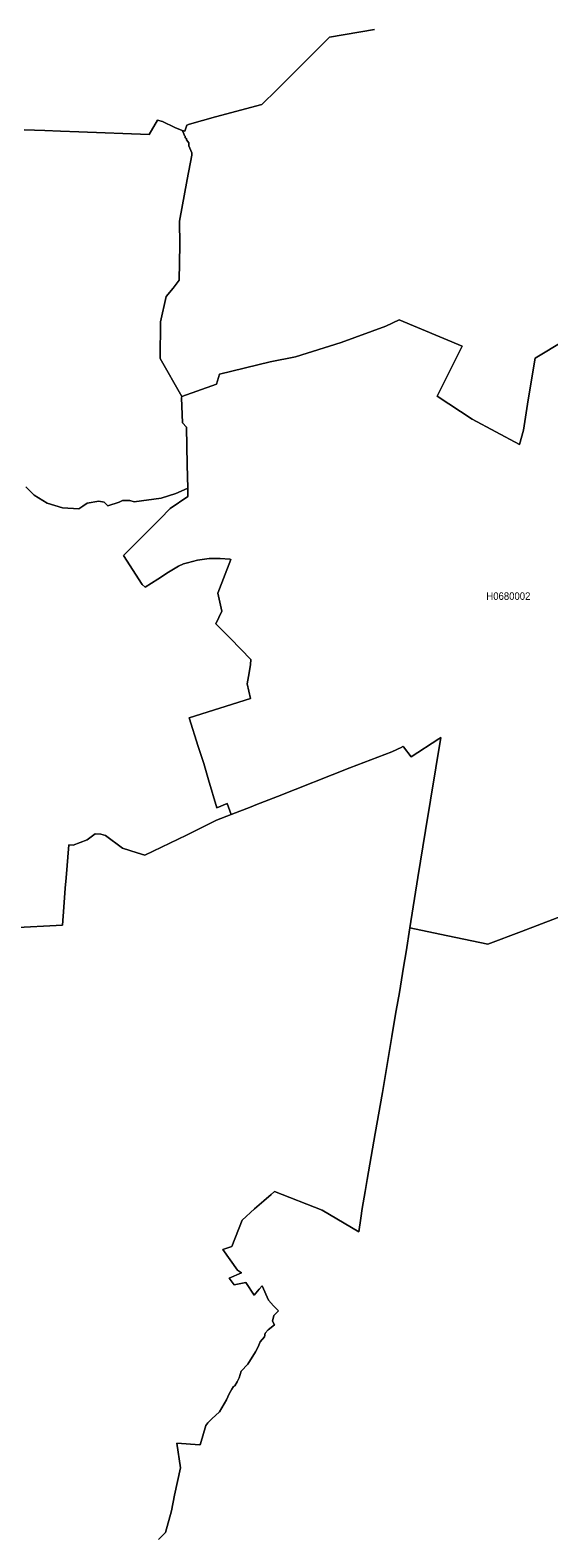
# Model space of a CAD drawing. Extents: x 369010 to 739155, y 6377141 to 6616555.
# Drawn here: x 495056 to 501969, y 6526211 to 6546276 of the extents above; entities that cross this region are included whole.
import ezdxf
from ezdxf.enums import TextEntityAlignment as Align

# ---------------------------------------------------------------- set-up
doc = ezdxf.new("R2010")
doc.units = 0
doc.header["$LTSCALE"] = 40
doc.layers.add('1', color=7, linetype='Continuous', lineweight=13)
doc.layers.add('2', color=7, linetype='Continuous')

msp = doc.modelspace()

# ---------------------------------------------------------------- linework, layer by layer
at = {"layer": '1'}
for points in [[(494977.62, 6544949.63), (495250.2, 6544939.2), (495459.07, 6544933.74), (495704.18, 6544923.31), (496644.41, 6544888.23), (496753.97, 6545079.05), (496821.83, 6545059.36), (496984.85, 6544979.42), (497082.5, 6544941.85), (497116.09, 6544933.41), (497145.88, 6545010.37), (497181.3, 6545026.09), (497527.04, 6545121.75), (498143.38, 6545286.1), (498343.47, 6545480.9), (498691.36, 6545828.12), (499045.54, 6546180.65), (499644.5, 6546285.25)], [(499644.5, 6546285.25), (499045.54, 6546180.65), (498691.36, 6545828.12), (498343.47, 6545480.9), (498143.38, 6545286.1), (497527.04, 6545121.75), (497181.3, 6545026.09), (497145.88, 6545010.37), (497116.09, 6544933.41), (497082.5, 6544941.85), (497103.35, 6544898.98), (497106.66, 6544876.48), (497124.2, 6544865.55), (497120.73, 6544843.71), (497141.25, 6544835.93), (497140.26, 6544818.38), (497171.21, 6544774.36), (497172.2, 6544735.63), (497209.44, 6544644.6), (497209.93, 6544614.15), (497147.7, 6544286.95), (497044.76, 6543735.49), (497051.05, 6543419.54), (497042.44, 6542947.36), (496963.66, 6542844.09), (496868.66, 6542731.05), (496793.03, 6542395.74), (496790.88, 6541908.33), (497076.37, 6541398.91), (497539.95, 6541563.91), (497579.5, 6541699.46), (498255.59, 6541862.65), (498592.39, 6541927.86), (499203.26, 6542118.85), (499795.93, 6542337.64), (499972.03, 6542419.9), (500813.62, 6542070.69), (500479.63, 6541407.35), (500948.67, 6541100.34), (501577.42, 6540763.54), (501628.72, 6540953.7), (501694.1, 6541354.55), (501784.46, 6541910.31), (502589.97, 6542395.57)], [(495000.79, 6540196.85), (495107.87, 6540089.6), (495284.79, 6539979.71), (495485.71, 6539920.79), (495705.34, 6539907.38), (495758.96, 6539939.66), (495817.88, 6539982.52), (495973.29, 6540006.52), (496042.96, 6539995.93), (496093.77, 6539947.6), (496243.89, 6539993.11), (496286.75, 6540014.63), (496383.24, 6540017.28), (496442.16, 6539998.58), (496803.79, 6540049.39), (496996.76, 6540108.31), (497149.86, 6540178.15), (497158.63, 6540182.12), (497148.7, 6540492.11), (497139.93, 6540993.42), (497084.98, 6541050.52), (497071.57, 6541385), (497076.37, 6541398.91), (496790.88, 6541908.33), (496793.03, 6542395.74), (496868.66, 6542731.05), (496963.66, 6542844.09), (497042.44, 6542947.36), (497051.05, 6543419.54), (497044.76, 6543735.49), (497147.7, 6544286.95), (497209.93, 6544614.15), (497209.44, 6544644.6), (497172.2, 6544735.63), (497171.21, 6544774.36), (497140.26, 6544818.38), (497141.25, 6544835.93), (497120.73, 6544843.71), (497124.2, 6544865.55), (497106.66, 6544876.48), (497103.35, 6544898.98), (497082.5, 6544941.85), (496984.85, 6544979.42), (496821.83, 6545059.36), (496753.97, 6545079.05), (496644.41, 6544888.23), (495704.18, 6544923.31), (495459.07, 6544933.74), (495250.2, 6544939.2), (494977.62, 6544949.63)], [(502589.97, 6542395.57), (501784.46, 6541910.31), (501694.1, 6541354.55), (501628.72, 6540953.7), (501577.42, 6540763.54), (500948.67, 6541100.34), (500479.63, 6541407.35), (500813.62, 6542070.69), (499972.03, 6542419.9), (499795.93, 6542337.64), (499203.26, 6542118.85), (498592.39, 6541927.86), (498255.59, 6541862.65), (497579.5, 6541699.46), (497539.95, 6541563.91), (497076.37, 6541398.91), (497071.57, 6541385), (497084.98, 6541050.52), (497139.93, 6540993.42), (497148.7, 6540492.11), (497158.63, 6540182.12), (497159.62, 6540150.51), (497159.62, 6540070.9), (496921.29, 6539908.54), (496786.91, 6539771.01), (496662.45, 6539648.2), (496299.66, 6539285.42), (496548.75, 6538897.31), (496591.11, 6538862.23), (496756.12, 6538970.13), (496898.46, 6539061.16), (497032.18, 6539143.58), (497099.71, 6539173.04), (497151.35, 6539188.93), (497286.4, 6539223.52), (497440.65, 6539244.04), (497587.94, 6539245.86), (497718.36, 6539234.28), (497729.45, 6539232.62), (497556, 6538782.45), (497611.45, 6538542.64), (497531.51, 6538373.99), (497728.29, 6538179.36), (497996.74, 6537901.31), (497992.77, 6537832.96), (497975.22, 6537723.72), (497946.59, 6537574.6), (497992.77, 6537381.96), (497176.34, 6537123.28), (497295.17, 6536740.63), (497372.46, 6536515.54), (497432.7, 6536297.24), (497543.92, 6535926.52), (497682.28, 6535982.13), (497735.57, 6535838.63), (498000.55, 6535940.42), (498064.6, 6535966.4), (498353.24, 6536078.95), (499318.62, 6536458.61), (499877.36, 6536673.6), (500010.92, 6536735.83), (500022.01, 6536745.26), (500032.77, 6536737.32), (500132.73, 6536604.25), (500502.3, 6536845.56), (500528.12, 6536862.11), (500324.88, 6535626.79), (500224.59, 6534998.37), (500115.69, 6534330.73), (500514.72, 6534245.49), (501155.55, 6534113.09), (501605.22, 6534281.74), (502286.11, 6534540.42)], [(497539.95, 6535760.68), (497735.57, 6535838.63), (497682.28, 6535982.13), (497543.92, 6535926.52), (497432.7, 6536297.24), (497372.46, 6536515.54), (497295.17, 6536740.63), (497176.34, 6537123.28), (497992.77, 6537381.96), (497946.59, 6537574.6), (497975.22, 6537723.72), (497992.77, 6537832.96), (497996.74, 6537901.31), (497728.29, 6538179.36), (497531.51, 6538373.99), (497611.45, 6538542.64), (497556, 6538782.45), (497729.45, 6539232.62), (497718.36, 6539234.28), (497587.94, 6539245.86), (497440.65, 6539244.04), (497286.4, 6539223.52), (497151.35, 6539188.93), (497099.71, 6539173.04), (497032.18, 6539143.58), (496898.46, 6539061.16), (496756.12, 6538970.13), (496591.11, 6538862.23), (496548.75, 6538897.31), (496299.66, 6539285.42), (496662.45, 6539648.2), (496786.91, 6539771.01), (496921.29, 6539908.54), (497159.62, 6540070.9), (497159.62, 6540150.51), (497158.63, 6540182.12), (497149.86, 6540178.15), (496996.76, 6540108.31), (496803.79, 6540049.39), (496442.16, 6539998.58), (496383.24, 6540017.28), (496286.75, 6540014.63), (496243.89, 6539993.11), (496093.77, 6539947.6), (496042.96, 6539995.93), (495973.29, 6540006.52), (495817.88, 6539982.52), (495758.96, 6539939.66), (495705.34, 6539907.38), (495485.71, 6539920.79), (495284.79, 6539979.71), (495107.87, 6540089.6), (495000.79, 6540196.85)], [(496765.56, 6526191.24), (496861.71, 6526284.09), (496938.67, 6526571.07), (496982.2, 6526779.77), (497058.17, 6527141.56), (497011.83, 6527469.76), (497315.69, 6527448.74), (497327.11, 6527462.48), (497397.95, 6527707.09), (497426.41, 6527744.16), (497478.05, 6527793.15), (497577.52, 6527888.48), (497672.68, 6528047.04), (497708.76, 6528125.98), (497745.17, 6528190.2), (497767.19, 6528224.13), (497785.72, 6528233.56), (497817, 6528286.85), (497841.5, 6528339.48), (497870.13, 6528429.52), (497957.85, 6528522.86), (498057.48, 6528688.86), (498096.54, 6528754.57), (498120.04, 6528818.95), (498181.44, 6528885.64), (498190.38, 6528934.3), (498228.11, 6528978.49), (498314.01, 6529046.35), (498288.19, 6529094.68), (498303.58, 6529172.46), (498364.99, 6529230.89), (498297.46, 6529299.74), (498231.92, 6529372.89), (498148.34, 6529565.7), (498107.63, 6529519.19), (498043.58, 6529441.57), (497930.04, 6529608.24), (497773.97, 6529578.44), (497709.42, 6529668.31), (497871.12, 6529739.98), (497817.5, 6529775.06), (497623.2, 6530048.31), (497741.86, 6530087.04), (497881.88, 6530439.4), (498047.55, 6530590.67), (498169.03, 6530695.93), (498267.5, 6530782.82), (498314.84, 6530822.21), (498947.89, 6530572.96), (499437.12, 6530285.48), (499461.28, 6530464.39), (499480.48, 6530596.29), (499521.36, 6530818.9), (499548.34, 6530979.27), (499655.09, 6531591.47), (499749.92, 6532139.45), (499876.87, 6532885.38), (499891.59, 6532968.96), (499935.62, 6533228.8), (499977.49, 6533471.1), (500033.76, 6533807.24), (500067.03, 6534011.14), (500115.69, 6534330.73), (500224.59, 6534998.37), (500324.88, 6535626.79), (500528.12, 6536862.11), (500502.3, 6536845.56), (500132.73, 6536604.25), (500032.77, 6536737.32), (500022.01, 6536745.26), (500010.92, 6536735.83), (499877.36, 6536673.6), (499318.62, 6536458.61), (498353.24, 6536078.95), (498064.6, 6535966.4), (498000.55, 6535940.42), (497735.57, 6535838.63)], [(497735.57, 6535838.63), (497539.95, 6535760.68), (497298.97, 6535642.51), (497140.59, 6535564.72), (496585.32, 6535296.94), (496483.7, 6535325.9), (496285.76, 6535387.97), (496058.36, 6535557.61), (495999.11, 6535576.47), (495922.97, 6535579.45), (495816.72, 6535502.16), (495627.88, 6535429.01), (495570.45, 6535433.48), (495534.87, 6534993.07), (495523.45, 6534858.85), (495504.91, 6534605.3), (495487.7, 6534363.5), (494805.66, 6534328.57)], [(494805.66, 6534328.57), (495487.7, 6534363.5), (495504.91, 6534605.3), (495523.45, 6534858.85), (495534.87, 6534993.07), (495570.45, 6535433.48), (495627.88, 6535429.01), (495816.72, 6535502.16), (495922.97, 6535579.45), (495999.11, 6535576.47), (496058.36, 6535557.61), (496285.76, 6535387.97), (496483.7, 6535325.9), (496585.32, 6535296.94), (497140.59, 6535564.72), (497298.97, 6535642.51), (497539.95, 6535760.68)], [(502709.63, 6534699.97), (502389.22, 6534579.81), (502286.11, 6534540.42), (501605.22, 6534281.74), (501155.55, 6534113.09), (500514.72, 6534245.49), (500115.69, 6534330.73)], [(500115.69, 6534330.73), (500067.03, 6534011.14), (500033.76, 6533807.24), (499977.49, 6533471.1), (499935.62, 6533228.8), (499891.59, 6532968.96), (499876.87, 6532885.38), (499749.92, 6532139.45), (499655.09, 6531591.47), (499548.34, 6530979.27), (499521.36, 6530818.9), (499480.48, 6530596.29), (499461.28, 6530464.39), (499437.12, 6530285.48), (498947.89, 6530572.96), (498314.84, 6530822.21), (498267.5, 6530782.82), (498169.03, 6530695.93), (498047.55, 6530590.67), (497881.88, 6530439.4), (497741.86, 6530087.04), (497623.2, 6530048.31), (497817.5, 6529775.06), (497871.12, 6529739.98), (497709.42, 6529668.31), (497773.97, 6529578.44), (497930.04, 6529608.24), (498043.58, 6529441.57), (498107.63, 6529519.19), (498148.34, 6529565.7), (498231.92, 6529372.89), (498297.46, 6529299.74), (498364.99, 6529230.89), (498303.58, 6529172.46), (498288.19, 6529094.68), (498314.01, 6529046.35), (498228.11, 6528978.49), (498190.38, 6528934.3), (498181.44, 6528885.64), (498120.04, 6528818.95), (498096.54, 6528754.57), (498057.48, 6528688.86), (497957.85, 6528522.86), (497870.13, 6528429.52), (497841.5, 6528339.48), (497817, 6528286.85), (497785.72, 6528233.56), (497767.19, 6528224.13), (497745.17, 6528190.2), (497708.76, 6528125.98), (497672.68, 6528047.04), (497577.52, 6527888.48), (497478.05, 6527793.15), (497426.41, 6527744.16), (497397.95, 6527707.09), (497327.11, 6527462.48), (497315.69, 6527448.74), (497011.83, 6527469.76), (497058.17, 6527141.56), (496982.2, 6526779.77), (496938.67, 6526571.07), (496861.71, 6526284.09), (496765.56, 6526191.24)]]:
    msp.add_lwpolyline(points, dxfattribs=at)

# ---------------------------------------------------------------- texts
at = {"layer": '2', "width": 0.95}
msp.add_text('H0680002', height=100, dxfattribs=at).set_placement((501429.24, 6538694.43), align=Align.CENTER)

doc.saveas('drawing.dxf')
